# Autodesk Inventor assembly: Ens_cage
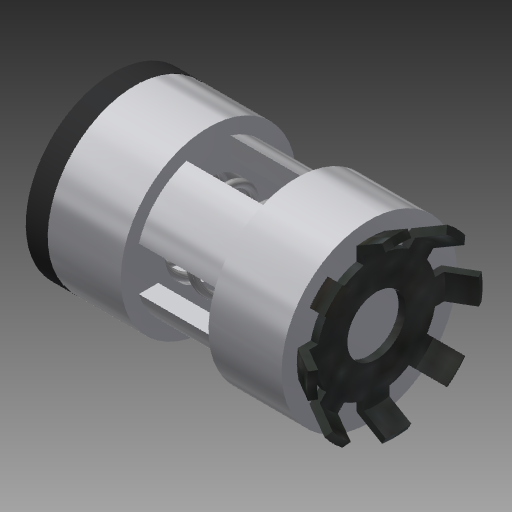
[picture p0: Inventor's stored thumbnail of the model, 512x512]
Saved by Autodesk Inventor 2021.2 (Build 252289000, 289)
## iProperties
Created: 2018-06
Part Number: Ens_cage
Material: Générique
Document SubType Name: Assembly
Designer: Fabian Perrée
Author: Fabian Perrée
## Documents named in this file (5)
- C:\Users\Fabian\Google Drive\04_CAO\01_Inventor\01_Fichiers_exercice_Inventor\01_Definitif\Capteur\Ens_cage\Ens_cage.iam
- C:\Users\Fabian\Google Drive\04_CAO\01_Inventor\01_Fichiers_exercice_Inventor\01_Definitif\Capteur\Ens_cage\Composants\Bouchon.ipt
- C:\Users\Fabian\Google Drive\04_CAO\01_Inventor\01_Fichiers_exercice_Inventor\01_Definitif\Capteur\Ens_cage\Composants\Rondelle.ipt
- C:\Users\Fabian\Google Drive\04_CAO\01_Inventor\01_Fichiers_exercice_Inventor\01_Definitif\Capteur\Ens_cage\Composants\Cage.ipt
- C:\Users\Fabian\Google Drive\04_CAO\01_Inventor\01_Fichiers_exercice_Inventor\01_Definitif\Capteur\Capteur\Design Accelerator\Ressort de compression11.ipt
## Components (4 placed, 4 different names)
1. Bouchon:1
2. Rondelle:1
3. Cage:1
4. Ressort de compression1:1
